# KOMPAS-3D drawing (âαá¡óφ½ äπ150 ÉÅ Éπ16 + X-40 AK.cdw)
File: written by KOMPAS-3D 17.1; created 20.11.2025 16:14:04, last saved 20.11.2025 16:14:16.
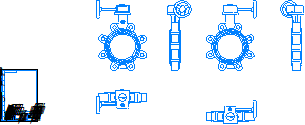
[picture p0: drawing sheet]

Sheet 1: A4, portrait

Title block, sheet 1: name: Гранвэл Ду150; material: Сталь 10  ГОСТ 1050-88; mass: 16,93; sheets: 1; sheet format: A4

Views: Вид 1, Спереди, Проекционный вид 2, Проекционный вид 3, Проекционный вид 4, Проекционный вид 5, Проекционный вид 6
Referenced files in \\adlc.lan\data\АДЛ_ПКД\3D-модели\ADL production\Дисковые поворотные затворы ГРАНВЭЛ\с резьбовыми проушинами с китайским редуктором Ру 16\KOMPAS 3D\: Гранвэл Ду150 РП Ру16 + X-40 AK.m3d
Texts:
  Andrey
  АДЛ
Dimensions and other numbers on the sheet: 1:1; 1; 16,93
